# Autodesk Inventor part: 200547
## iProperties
Created: 2007-10
Part Number: 200547
Document SubType Name: Modeling
Designer: TH
Density: 7.85 g/cm^3
Mass: 510.334 g
Surface Area: 671.811 cm^2
Volume: 65.0106 cm^3
Material: Steel
Description: RAIL SIDE - LEFT OUTER
Component Category: Lower Component
Author: TH
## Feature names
1. TaggingFeature3
